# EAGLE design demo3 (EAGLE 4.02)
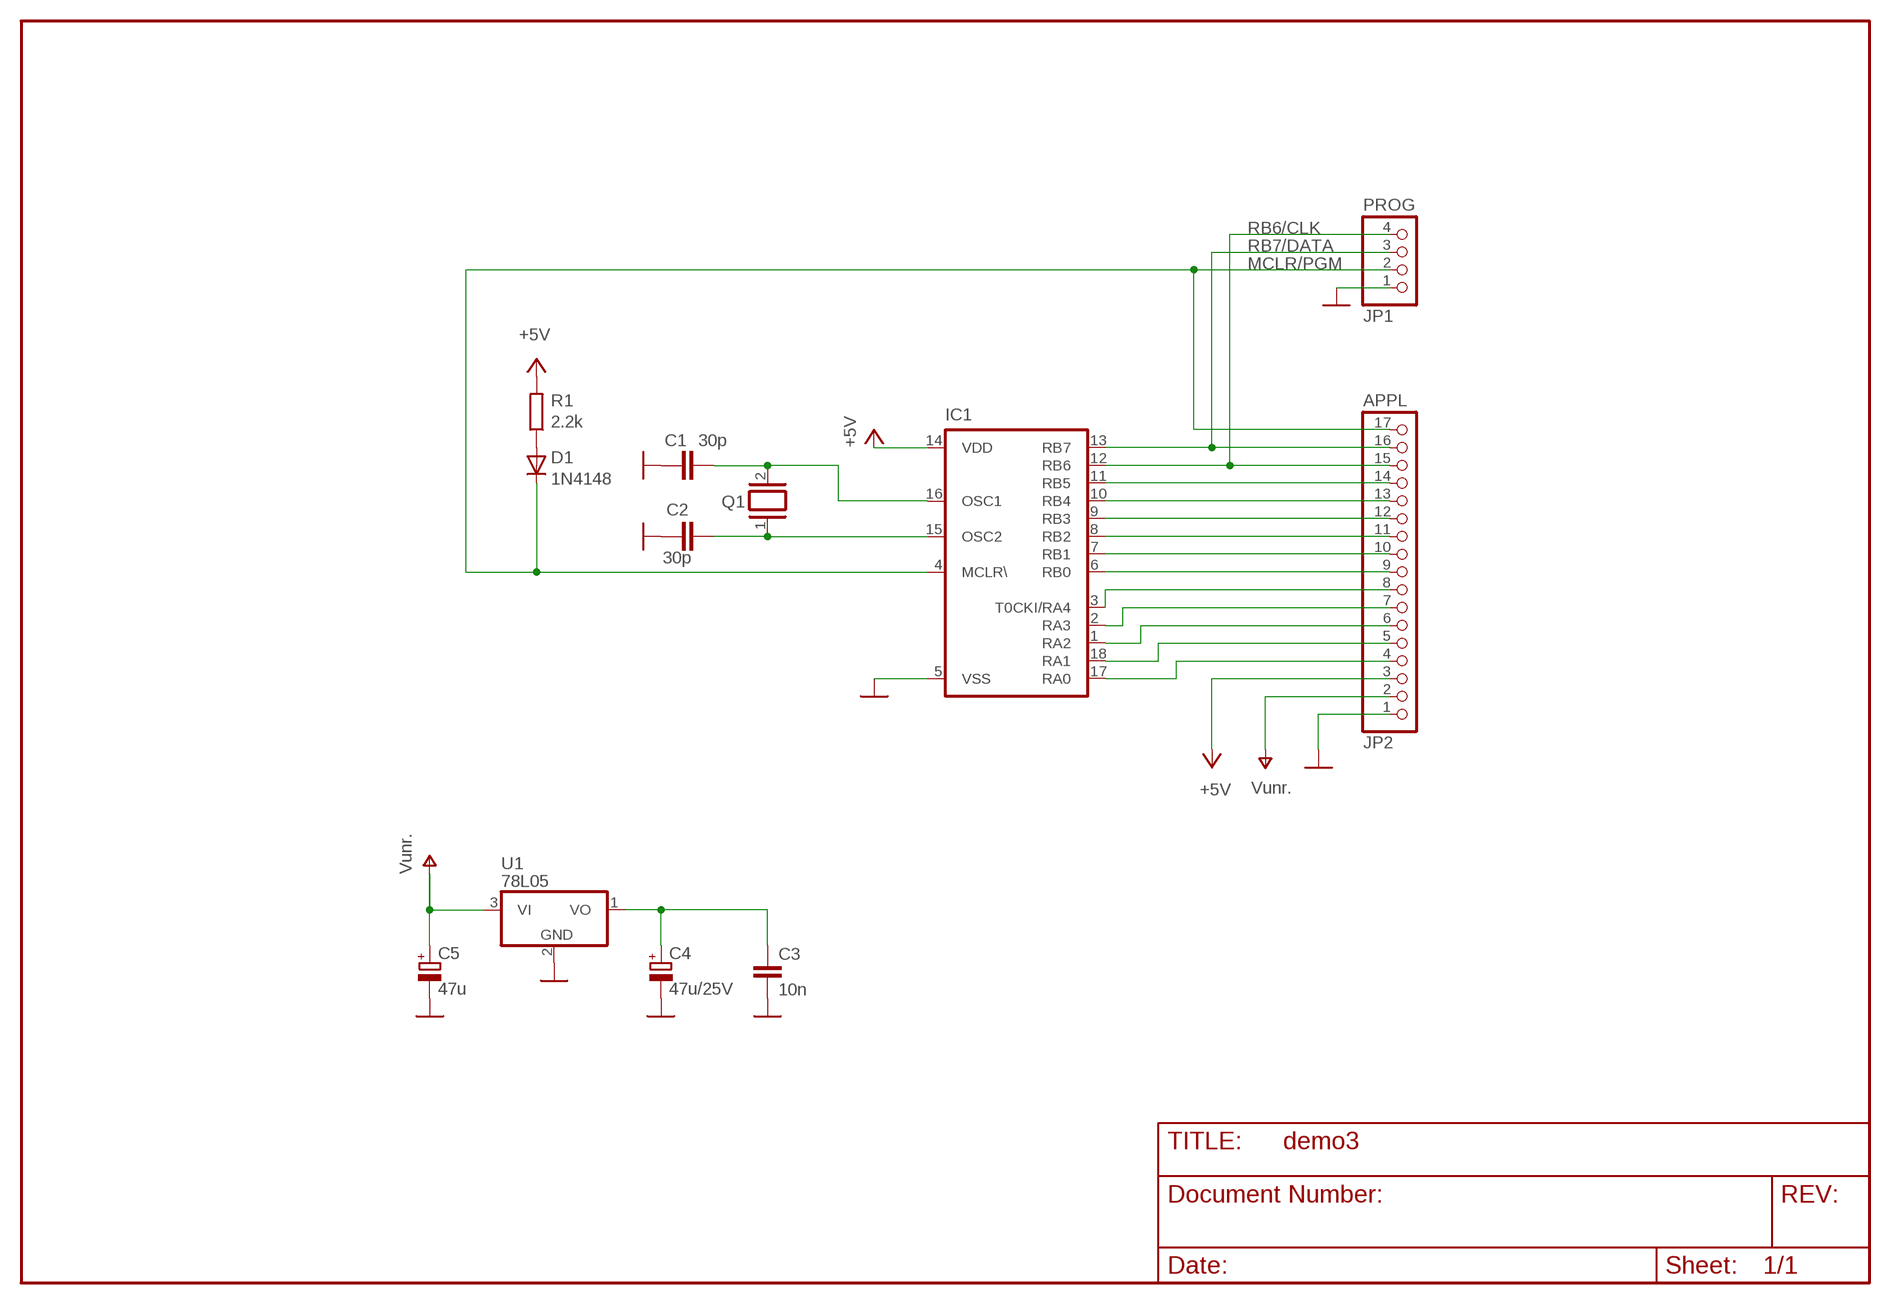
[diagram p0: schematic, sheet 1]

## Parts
C1  30p  C-EUC1206  [C1206]
C2  30p  C-EUC1206  [C1206]
C3  10n  C-EU025-025X050  [C025-025X050]
C4  47u/25V  CPOL-TAP5-45  [TAP5-45]
C5  47u  CPOL-TAP5-45  [TAP5-45]
D1  1N4148  [DO35-10]
IC1  PIC16F84ASO  [SO-18W]
JP1  PROG  PINHD-1X4  [1X04]
JP2  APPL  PINHD-1X17  [1X17]
Q1  XTAL/S  [QS]
R1  2.2k  R-EU_R1206  [R1206]
U1  78L05  78LXXZ  [TO92]

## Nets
GND [power]: C1.2 C2.2 C3.1 C4.- C5.- IC1.5(VSS) JP1.1 JP2.1 U1.2(GND)
MCLR/PGM: D1.K IC1.4(MCLR\) JP1.2 JP2.17
N$1: C3.2 C4.+ U1.1(VO)
N$2: C1.1 IC1.16(OSC1) Q1.2
N$3: C2.1 IC1.15(OSC2) Q1.1
N$5: D1.A R1.1
RA0: IC1.17(RA0) JP2.4
RA1: IC1.18(RA1) JP2.5
RA2: IC1.1(RA2) JP2.6
RA3: IC1.2(RA3) JP2.7
RA4: IC1.3(T0CKI/RA4) JP2.8
RB0: IC1.6(RB0) JP2.9
RB1: IC1.7(RB1) JP2.10
RB2: IC1.8(RB2) JP2.11
RB3: IC1.9(RB3) JP2.12
RB4: IC1.10(RB4) JP2.13
RB5: IC1.11(RB5) JP2.14
RB6/CLK: IC1.12(RB6) JP1.4 JP2.15
RB7/DATA: IC1.13(RB7) JP1.3 JP2.16
V+ [power]: C5.+ JP2.2 U1.3(VI) ; supply symbol labelled Vunr.
VCC [power]: IC1.14(VDD) JP2.3 R1.2 ; supply symbol labelled +5V

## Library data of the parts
C1-C3 = rcl:C-EU: capacitor EUrop Symbol
C4 C5 = rcl:CPOL-: polarity capacitor (Tantalum, Electrolyt) EUrop Symbol
D1 = diode:1N4148: 1N4148 - High Conductance Fast Diode
IC1 = microchip:PIC16F8*: 8-Bit Microcontroller PIC16F8X Family - CMOS Flash/EEPROM Pin Compatible : PIC16F83, PIC16CR83, PIC16F84A, PIC16CR84 see also PIC16C*
JP1 = PINHEAD:PINHD-1X4
JP2 = PINHEAD:PINHD-1X17
Q1 = special:XTAL/S
R1 = rcl:R-EU_: resistor EUrop Symbol
U1 = linear:78LXXZ: positiv voltage regulator / low power TO92

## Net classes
0 default: width 0.2 mm, drill 0.2 mm, clearance 0.4 mm
1 power: width 0.4 mm, drill 0.2 mm, clearance 0.4 mm

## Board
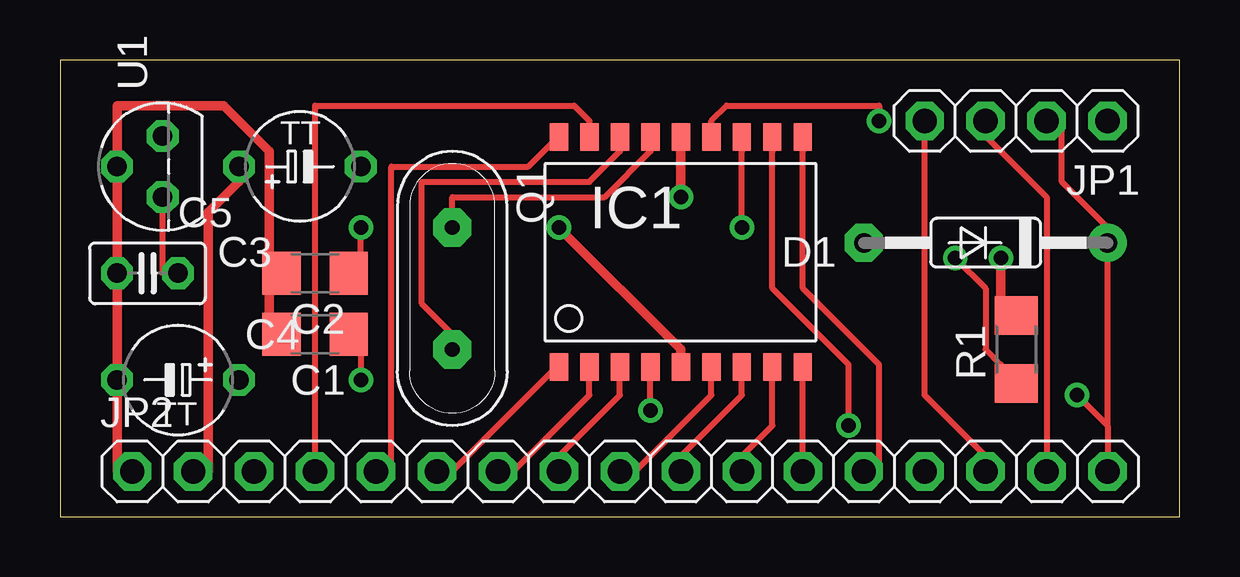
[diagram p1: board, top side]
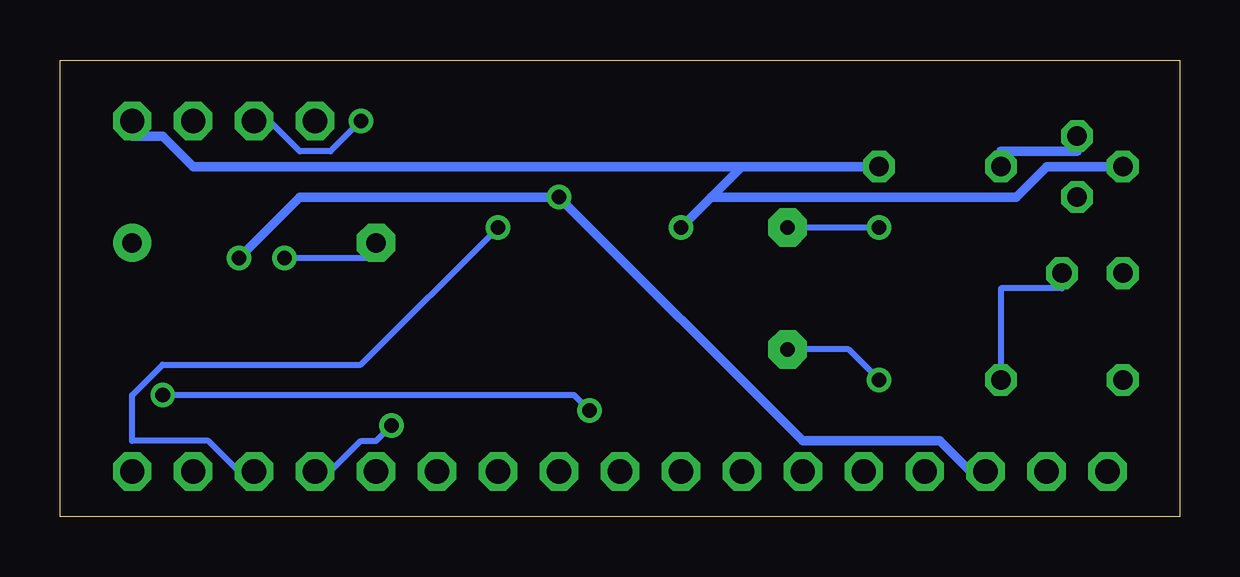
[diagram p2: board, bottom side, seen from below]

Size 46.66 x 19.04 mm. Coordinates in mm from the lower left corner, seen from the top.
Outline: 0,0 46.66,0 46.66,19.04 0,19.04 0,0
Copper layers used: Top, Bottom

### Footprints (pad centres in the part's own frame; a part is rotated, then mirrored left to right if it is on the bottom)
C1206 = smd 1.6 x 1.8: 1 -1.4,0; 2 1.4,0
C025-025X050 = drill 0.813 octagon: 1 -1.27,0; 2 1.27,0
TAP5-45 = drill 0.813 octagon: + 2.54,0; - -2.54,0
DO35-10 = drill 0.813 pad 1.6 octagon: A 5.08,0 | drill 0.813 pad 1.6 round: K -5.08,0
SO-18W = smd 0.762 x 1.143: 1 -5.08,-4.788; 2 -3.81,-4.788; 3 -2.54,-4.788; 4 -1.27,-4.788; 5 0,-4.788; 6 1.27,-4.788; 7 2.54,-4.788; 8 3.81,-4.788; 9 5.08,-4.788; 10 5.08,4.788; 11 3.81,4.788; 12 2.54,4.788; 13 1.27,4.788; 14 0,4.788; 15 -1.27,4.788; 16 -2.54,4.788; 17 -3.81,4.788; 18 -5.08,4.788
1X04 = drill 1.016 pad 1.6 octagon: 1 -3.81,0; 2 -1.27,0; 3 1.27,0; 4 3.81,0
1X17 = drill 1.016 pad 1.6 octagon: 1 -20.32,0; 2 -17.78,0; 3 -15.24,0; 4 -12.7,0; 5 -10.16,0; 6 -7.62,0; 7 -5.08,0; 8 -2.54,0; 9 0,0; 10 2.54,0; 11 5.08,0; 12 7.62,0; 13 10.16,0; 14 12.7,0; 15 15.24,0; 16 17.78,0; 17 20.32,0
QS = drill 0.61 pad 1.6 octagon: 1 -2.54,0; 2 2.54,0
R1206 = smd 1.6 x 1.803: 1 -1.422,0; 2 1.422,0
TO92 = drill 0.813 octagon: 1 -1.27,0; 2 0,1.905; 3 1.27,0

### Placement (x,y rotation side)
C1  10.63,7.62 180 top
C2  10.63,10.16 180 top
C3  3.65,10.16 0 top
C4  4.92,5.71 0 top
C5  10,14.6 180 top
D1  38.57,11.43 180 top
IC1  25.87,11.04 0 top
JP1  39.84,16.5 180 top
JP2  23.33,1.9 0 top
Q1  16.34,9.52 270 top
R1  39.84,6.98 90 top
U1  4.28,14.6 90 top

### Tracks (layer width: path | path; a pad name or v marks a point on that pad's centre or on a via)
GND  (via drill 0.61)
  Top 0.4: C1.2 8.72,8.25 8.72,9.52 C2.2 8.72,10.79 8.72,15.24 6.82,17.14 2.38,17.14 U1.2 C3.1 C4.- 2.38,1.9 JP2.1 | v20.79,12.06 25.87,6.98 25.87,6.34 25.84,6.22
  Top 0.406: IC1.5 25.74,6.26 25.74,6.22 25.84,6.22
  Bottom 0.4: 19.52,13.33 18.25,14.6 | 19.52,13.33 v20.79,12.06 | 18.25,14.6 C5.- | 18.25,14.6 41.11,14.6 42.38,15.87 43.65,15.87 JP1.1 | 19.52,13.33 6.82,13.33 5.55,14.6 U1.2
MCLR/PGM  (via drill 0.61)
  Top 0.254: v24.6,4.44 24.6,5.71 24.57,6.22 | v42.38,5.08 43.65,3.8 | 43.65,3.8 JP2.17 | 43.65,3.8 D1.K 43.65,12.06 41.75,13.97 41.75,16.5 JP1.2
  Top 0.406: 24.57,6.22 24.6,6.22 IC1.4
  Bottom 0.254: v24.6,4.44 25.23,5.08 v42.38,5.08
N$1
  Top 0.254: C3.2 4.28,10.16 U1.1
  Bottom 0.254: C4.+ 7.46,9.52 4.92,9.52 C3.2
N$2  (via drill 0.61)
  Top 0.254: 23.3,15.79 23.33,15.24 22.06,13.97 15.08,13.97 15.08,8.89 16.34,7.62 Q1.2 | v12.54,5.71 12.54,6.98 C1.1
  Top 0.406: 23.2,15.83 23.2,15.87 | 23.2,15.83 IC1.16 | 23.3,15.79 23.2,15.79 23.2,15.83
  Bottom 0.254: v12.54,5.71 13.8,6.98 Q1.2
N$3  (via drill 0.61)
  Top 0.254: 24.57,15.79 24.6,15.24 22.69,13.33 16.34,13.33 Q1.1 | v12.54,12.06 12.54,10.79 C2.1
  Top 0.406: 24.57,15.79 24.6,15.79 IC1.15 24.6,15.87
  Bottom 0.254: v12.54,12.06 Q1.1
N$5  (via drill 0.61)
  Top 0.254: v37.3,10.79 38.57,9.52 38.57,6.98 39.21,6.34 R1.1
  Bottom 0.254: v37.3,10.79 33.49,10.79 D1.A
RA0
  Top 0.254: 22.04,15.79 22.06,15.87 22.06,16.5 21.42,17.14 10.63,17.14 JP2.4
  Top 0.406: 22.06,15.87 IC1.17 22.06,15.74
RA1
  Top 0.254: 20.76,15.79 20.79,15.87 19.52,14.6 13.8,14.6 13.8,1.9 JP2.5
  Top 0.406: 20.79,15.87 IC1.18
RA2
  Top 0.254: 20.76,6.22 20.79,6.34 16.34,1.9 JP2.6
  Top 0.406: IC1.1 20.79,6.22 20.76,6.22
RA3
  Top 0.254: 22.04,6.22 22.06,5.71 22.06,5.08 18.88,1.9 JP2.7
  Top 0.406: 22.04,6.22 22.06,6.22 IC1.2
RA4
  Top 0.254: 23.3,6.22 23.33,5.71 23.33,5.08 20.79,2.54 JP2.8
  Top 0.406: IC1.3 23.33,6.22 23.3,6.22
RB0
  Top 0.254: 27.11,6.22 27.14,5.71 27.14,5.08 23.96,1.9 JP2.9
  Top 0.406: 27.11,6.22 27.14,6.22 IC1.6
RB1
  Top 0.254: 28.38,6.22 28.41,5.71 28.41,5.08 25.87,2.54 JP2.10
  Top 0.406: 28.38,6.22 28.41,6.22 IC1.7 28.41,6.34
RB2
  Top 0.254: 29.65,6.22 29.68,5.71 29.68,3.8 28.41,2.54 JP2.11
  Top 0.406: 29.65,6.22 29.68,6.22 IC1.8
RB3
  Top 0.254: 30.92,6.22 30.95,5.71 JP2.12
  Top 0.406: IC1.9 30.82,6.26 30.82,6.22 30.92,6.22
RB4
  Top 0.254: 30.92,15.79 30.95,15.24 30.95,9.52 34.12,6.34 34.12,1.9 JP2.13
  Top 0.406: 30.92,15.79 30.95,15.79 IC1.10 30.95,15.87
RB5  (via drill 0.61)
  Top 0.254: v32.85,3.8 32.85,6.34 29.68,9.52 29.68,15.24 29.65,15.79
  Top 0.406: 29.81,15.83 29.81,15.79 29.65,15.79 | 29.81,15.83 IC1.11 | 29.81,15.83 29.81,15.87
  Bottom 0.254: v32.85,3.8 33.49,3.17 34.12,3.17 35.4,1.9 JP2.14
RB6/CLK  (via drill 0.61)
  Top 0.254: v28.41,12.06 28.41,15.24 28.38,15.79 | JP1.4 36.03,5.08 38.57,2.54 JP2.15
  Top 0.406: 28.41,15.79 IC1.12 | 28.38,15.79 28.41,15.79 | 28.41,15.79 28.41,15.74
  Bottom 0.254: v28.41,12.06 34.12,6.34 42.38,6.34 43.65,5.08 43.65,3.17 40.48,3.17 39.21,1.9 JP2.15
RB7/DATA  (via drill 0.61)
  Top 0.254: v34.12,16.5 34.12,17.14 27.77,17.14 27.14,16.5 27.14,15.87 27.11,15.79 | JP2.16 41.11,13.33 38.57,15.87 JP1.3
  Top 0.406: 27.14,15.87 IC1.13
  Bottom 0.254: v34.12,16.5 35.4,15.24 36.66,15.24 37.94,16.5 JP1.3
V+
  Top 0.4: JP2.2 6.19,1.9 6.19,12.7 7.46,13.97 C5.+
  Bottom 0.4: U1.3 4.28,15.24 7.46,15.24 C5.+
VCC  (via drill 0.61)
  Top 0.4: v25.87,13.33 25.87,15.24 25.84,15.79 | v39.21,10.79 39.21,8.89 R1.2
  Top 0.406: 26,15.83 26,15.79 25.84,15.79 | 26,15.83 IC1.14 | 26,15.83 26,15.87
  Bottom 0.4: JP2.3 8.72,1.9 10,3.17 15.71,3.17 v25.87,13.33 36.66,13.33 v39.21,10.79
